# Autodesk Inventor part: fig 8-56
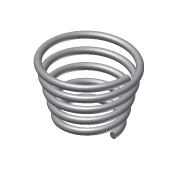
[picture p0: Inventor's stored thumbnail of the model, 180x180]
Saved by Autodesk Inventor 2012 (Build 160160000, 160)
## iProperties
Shininess: 77.0
Length Units: 11269
Angle Units: 11279
Time Units: 11290
Mass Units: 11283
Length Display Precision: 3
Angle Display Precision: 2
Created: 2002-01
Part Number: fig 8-56
Document SubType Name: Modeling
Designer: CADSoft
Density: 1 g/cm^3
Material: Default
Density: 0.0
Volumn: 0.0
Area: 0.0
PropertySet Name: Model Information
Control State: 0
Master: False
Checked Out: False
Author: CADSoft
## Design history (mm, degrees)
sketch "Sketch2"
  geometry: C1 r 2.5 at (-19.895, -0.092)
  constraints: 1 centre point
  dimensions: "d0" = 5 diameter of C1
coil "Coil5" sketch "Sketch2" pitch "d35" = 10; turns "d37" = 5; dims "d36" = 10, "d38" = 15 deg, angle "d39" = 90 deg, angle "d40" = 90 deg, "d41" = 0, "d42" = 0
body "Solid1"
